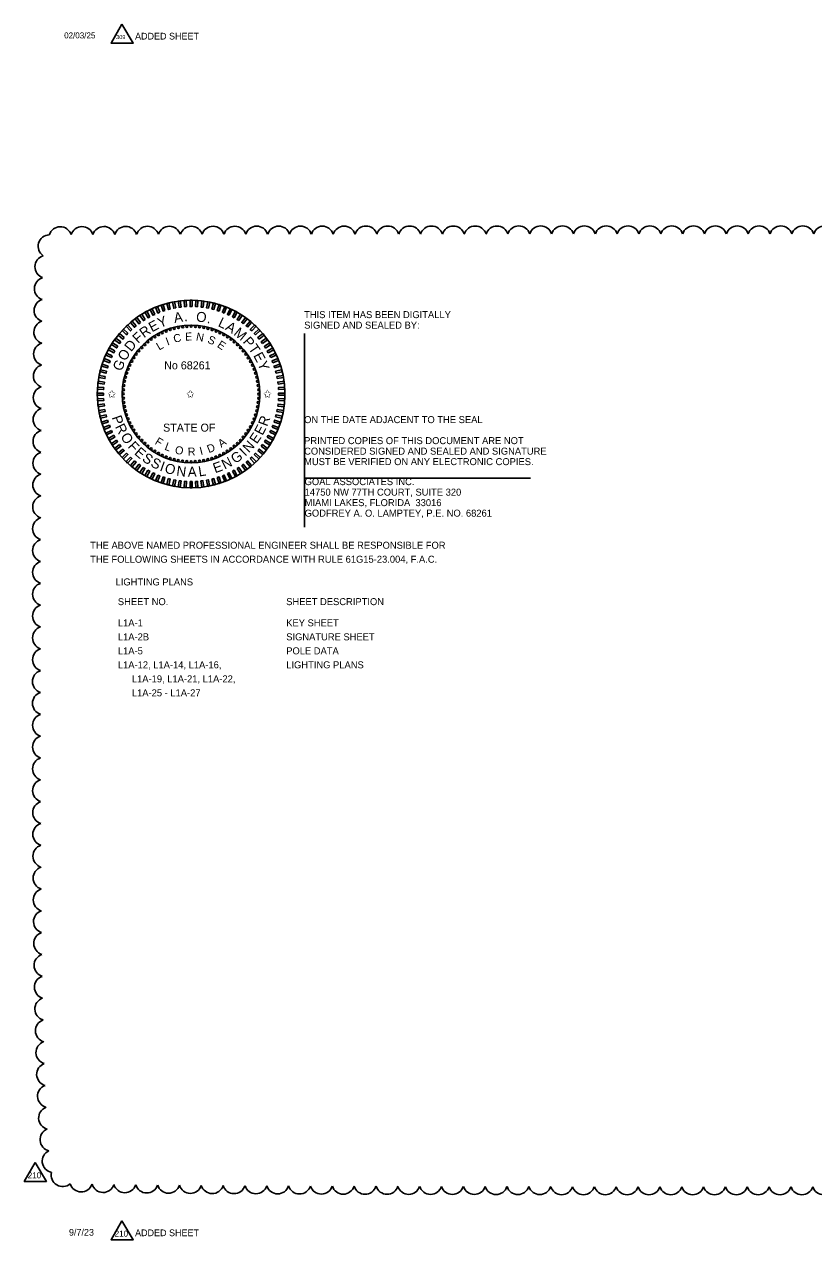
# Model space of a CAD drawing. Extents: x -811.2 to -795.1, y -2238.2 to -2204.
# Drawn here: x -811.16 to -803.27, y -2237.98 to -2225.83 of the extents above; entities that cross this region are included whole.
import ezdxf

# ---------------------------------------------------------------- set-up
doc = ezdxf.new("R2010")
doc.units = 0
for name, color, linetype in [('AdhocPoint_dp', 7, 'Continuous'), ('Cloud_dp', 7, 'Continuous'), ('PlotBorder_dp', 7, 'Continuous'), ('TextMinor', 7, 'Continuous'), ('TextMisc', 7, 'Continuous'), ('TextShtNo', 7, 'Continuous')]:
    doc.layers.add(name, color=color, linetype=linetype)

msp = doc.modelspace()

# ---------------------------------------------------------------- linework, layer by layer
at = {"layer": 'AdhocPoint_dp'}
for p, q in [((-808.355, -2228.92), (-808.355, -2230.855)), ((-808.355, -2230.365), (-806.098, -2230.365))]:
    msp.add_line(p, q, dxfattribs=at)
at = {"layer": 'Cloud_dp'}
for points in [[(-810.181, -2225.827), (-810.289, -2226.015), (-810.068, -2226.015)], [(-811.049, -2237.21), (-811.157, -2237.398), (-810.937, -2237.398)], [(-810.181, -2237.792), (-810.289, -2237.98), (-810.068, -2237.98)]]:
    msp.add_lwpolyline(points, close=True, dxfattribs=at)
for centre, start, end in [((-810.905, -2228.046), 91.4771, 236.4771), ((-810.798, -2227.965), 18.0566, 163.0566), ((-810.58, -2227.964), 17.7998, 162.7998), ((-810.362, -2227.963), 17.7187, 162.7187), ((-810.143, -2227.962), 17.6743, 162.6743), ((-809.925, -2227.961), 17.6451, 162.6451), ((-809.707, -2227.961), 17.624, 162.624), ((-809.488, -2227.961), 17.6079, 162.6079), ((-809.27, -2227.96), 17.5951, 162.5951), ((-809.052, -2227.96), 17.5845, 162.5845), ((-808.834, -2227.959), 17.5756, 162.5756), ((-808.615, -2227.959), 17.568, 162.568), ((-808.397, -2227.959), 17.5614, 162.5614), ((-808.179, -2227.959), 17.5556, 162.5556), ((-807.96, -2227.959), 17.5505, 162.5505), ((-807.742, -2227.958), 17.5459, 162.5459), ((-807.524, -2227.958), 17.5417, 162.5417), ((-807.305, -2227.958), 17.5379, 162.5379), ((-807.087, -2227.958), 17.5344, 162.5344), ((-806.869, -2227.958), 17.5313, 162.5313), ((-806.65, -2227.958), 17.5283, 162.5283), ((-806.432, -2227.958), 17.5256, 162.5256), ((-806.214, -2227.957), 17.5231, 162.5231), ((-805.995, -2227.957), 17.5207, 162.5207), ((-805.777, -2227.957), 17.5185, 162.5185), ((-805.559, -2227.957), 17.5164, 162.5164), ((-805.34, -2227.957), 17.5145, 162.5145), ((-805.122, -2227.957), 17.5126, 162.5126), ((-804.904, -2227.957), 17.5109, 162.5109), ((-804.685, -2227.957), 17.5092, 162.5092), ((-804.467, -2227.957), 17.5077, 162.5077), ((-804.249, -2227.957), 17.5062, 162.5062), ((-804.03, -2227.957), 17.5048, 162.5048), ((-803.812, -2227.957), 17.5034, 162.5034), ((-803.594, -2227.957), 17.5021, 162.5021), ((-803.375, -2227.957), 17.5009, 162.5009), ((-803.157, -2227.957), 17.5, 162.5), ((-810.937, -2228.252), 105.908, 250.908), ((-810.942, -2228.47), 106.4168, 251.4168), ((-810.945, -2228.688), 106.6762, 251.6762), ((-810.948, -2228.906), 106.841, 251.841), ((-810.95, -2229.124), 106.9576, 251.9576), ((-810.952, -2229.343), 107.0457, 252.0457), ((-810.954, -2229.561), 107.1154, 252.1154), ((-810.955, -2229.779), 107.1722, 252.1722), ((-810.956, -2229.998), 107.2198, 252.2198), ((-810.957, -2230.216), 107.2603, 252.2603), ((-810.958, -2230.434), 107.2954, 252.2954), ((-810.959, -2230.652), 107.3262, 252.3262), ((-810.96, -2230.871), 107.3535, 252.3535), ((-810.96, -2231.089), 107.3779, 252.3779), ((-810.96, -2231.307), 107.3998, 252.3998), ((-810.961, -2231.526), 107.4198, 252.4198), ((-810.961, -2231.744), 107.438, 252.438), ((-810.961, -2231.962), 107.4547, 252.4547), ((-810.961, -2232.181), 107.4701, 252.4701), ((-810.962, -2232.399), 107.4843, 252.4843), ((-810.962, -2232.617), 107.499, 252.499), ((-810.961, -2232.836), 107.5356, 252.5356), ((-810.961, -2233.054), 107.5822, 252.5822), ((-810.961, -2233.272), 107.6325, 252.6325), ((-810.96, -2233.49), 107.6869, 252.6869), ((-810.959, -2233.709), 107.7461, 252.7461), ((-810.958, -2233.927), 107.8108, 252.8108), ((-810.957, -2234.145), 107.8818, 252.8818), ((-810.955, -2234.364), 107.9604, 252.9604), ((-810.954, -2234.582), 108.0479, 253.0479), ((-810.951, -2234.8), 108.1461, 253.1461), ((-810.949, -2235.018), 108.2576, 253.2576), ((-810.945, -2235.237), 108.3854, 253.3854), ((-810.942, -2235.455), 108.534, 253.534), ((-810.938, -2235.673), 108.7099, 253.7099), ((-810.932, -2235.891), 108.9225, 253.9225), ((-810.927, -2236.109), 109.1867, 254.1867), ((-810.92, -2236.327), 109.5275, 254.5275), ((-810.911, -2236.545), 109.9909, 254.9909), ((-810.9, -2236.763), 110.6749, 255.6749), ((-810.886, -2236.98), 111.8417, 256.8417), ((-810.864, -2237.195), 114.6718, 259.6718), ((-810.774, -2237.335), 166.2299, 311.2299), ((-810.588, -2237.389), 196.1072, 341.1072), ((-810.37, -2237.394), 196.5738, 341.5738), ((-810.152, -2237.397), 196.7877, 341.7877), ((-809.934, -2237.399), 196.9179, 341.9179), ((-809.715, -2237.401), 197.008, 342.008), ((-809.497, -2237.403), 197.075, 342.075), ((-809.279, -2237.405), 197.1274, 342.1274), ((-809.061, -2237.406), 197.1699, 342.1699), ((-808.842, -2237.407), 197.2052, 342.2052), ((-808.624, -2237.408), 197.2352, 342.2352), ((-808.406, -2237.409), 197.261, 342.261), ((-808.187, -2237.41), 197.2836, 342.2836), ((-807.969, -2237.411), 197.3036, 342.3036), ((-807.751, -2237.412), 197.3214, 342.3214), ((-807.532, -2237.412), 197.3374, 342.3374), ((-807.314, -2237.413), 197.3519, 342.3519), ((-807.096, -2237.413), 197.3651, 342.3651), ((-806.878, -2237.414), 197.3773, 342.3773), ((-806.659, -2237.414), 197.3884, 342.3884), ((-806.441, -2237.415), 197.3987, 342.3987), ((-806.223, -2237.415), 197.4083, 342.4083), ((-806.004, -2237.415), 197.4172, 342.4172), ((-805.786, -2237.416), 197.4256, 342.4256), ((-805.568, -2237.416), 197.4334, 342.4334), ((-805.349, -2237.416), 197.4407, 342.4407), ((-805.131, -2237.417), 197.4476, 342.4476), ((-804.913, -2237.417), 197.4542, 342.4542), ((-804.694, -2237.417), 197.4604, 342.4604), ((-804.476, -2237.417), 197.4662, 342.4662), ((-804.258, -2237.417), 197.4718, 342.4718), ((-804.039, -2237.417), 197.4771, 342.4771), ((-803.821, -2237.417), 197.4821, 342.4821), ((-803.603, -2237.417), 197.487, 342.487), ((-803.384, -2237.417), 197.4916, 342.4916), ((-803.166, -2237.417), 197.496, 342.496)]:
    msp.add_arc(centre, 0.114, start, end, dxfattribs=at)
at = {"layer": 'TextMinor'}
for radius in [0.938, 0.688]:
    msp.add_circle((-809.49, -2229.524), radius, dxfattribs=at)
at = {"layer": 'TextShtNo'}
for p, q in [((-809.5, -2230.461), (-809.5, -2230.399)), ((-809.49, -2230.461), (-809.49, -2230.399)), ((-809.48, -2230.461), (-809.48, -2230.399))]:
    msp.add_line(p, q, dxfattribs=at)
for points in [[(-809.853, -2228.728), (-809.872, -2228.736), (-809.898, -2228.68), (-809.88, -2228.671)], [(-809.803, -2228.706), (-809.822, -2228.714), (-809.845, -2228.656), (-809.826, -2228.648)], [(-809.751, -2228.688), (-809.77, -2228.695), (-809.789, -2228.635), (-809.77, -2228.629)], [(-809.698, -2228.674), (-809.717, -2228.679), (-809.733, -2228.618), (-809.713, -2228.613)], [(-809.644, -2228.662), (-809.664, -2228.666), (-809.676, -2228.605), (-809.656, -2228.601)], [(-809.59, -2228.654), (-809.61, -2228.657), (-809.618, -2228.595), (-809.598, -2228.592)], [(-809.535, -2228.65), (-809.555, -2228.651), (-809.559, -2228.589), (-809.539, -2228.588)], [(-809.48, -2228.649), (-809.5, -2228.649), (-809.5, -2228.586), (-809.48, -2228.586)], [(-809.425, -2228.651), (-809.445, -2228.65), (-809.441, -2228.588), (-809.421, -2228.589)], [(-809.37, -2228.657), (-809.39, -2228.654), (-809.383, -2228.592), (-809.363, -2228.595)], [(-809.316, -2228.666), (-809.336, -2228.662), (-809.324, -2228.601), (-809.304, -2228.605)], [(-809.263, -2228.679), (-809.282, -2228.674), (-809.267, -2228.613), (-809.247, -2228.618)], [(-809.21, -2228.695), (-809.229, -2228.689), (-809.21, -2228.629), (-809.191, -2228.635)], [(-809.159, -2228.714), (-809.177, -2228.707), (-809.154, -2228.649), (-809.136, -2228.656)], [(-809.108, -2228.736), (-809.127, -2228.728), (-809.1, -2228.671), (-809.082, -2228.68)], [(-810.04, -2228.843), (-810.056, -2228.856), (-810.095, -2228.808), (-810.08, -2228.795)], [(-809.996, -2228.81), (-810.013, -2228.822), (-810.049, -2228.771), (-810.033, -2228.759)], [(-809.95, -2228.78), (-809.967, -2228.79), (-810.001, -2228.738), (-809.984, -2228.727)], [(-809.903, -2228.752), (-809.92, -2228.762), (-809.951, -2228.707), (-809.933, -2228.697)], [(-809.06, -2228.762), (-809.077, -2228.752), (-809.047, -2228.697), (-809.03, -2228.707)], [(-809.013, -2228.79), (-809.03, -2228.78), (-808.996, -2228.727), (-808.979, -2228.738)], [(-808.968, -2228.822), (-808.984, -2228.81), (-808.947, -2228.76), (-808.931, -2228.771)], [(-808.925, -2228.856), (-808.94, -2228.843), (-808.9, -2228.795), (-808.885, -2228.808)], [(-810.158, -2228.958), (-810.171, -2228.974), (-810.219, -2228.934), (-810.206, -2228.918)], [(-810.121, -2228.917), (-810.135, -2228.932), (-810.18, -2228.889), (-810.167, -2228.875)], [(-810.082, -2228.879), (-810.096, -2228.893), (-810.139, -2228.847), (-810.124, -2228.833)], [(-808.884, -2228.893), (-808.898, -2228.879), (-808.856, -2228.834), (-808.841, -2228.847)], [(-808.845, -2228.932), (-808.859, -2228.918), (-808.814, -2228.875), (-808.8, -2228.89)], [(-808.809, -2228.974), (-808.822, -2228.958), (-808.774, -2228.919), (-808.761, -2228.934)], [(-810.223, -2229.046), (-810.234, -2229.063), (-810.287, -2229.03), (-810.276, -2229.013)], [(-810.192, -2229.001), (-810.204, -2229.018), (-810.254, -2228.981), (-810.243, -2228.965)], [(-808.776, -2229.018), (-808.788, -2229.001), (-808.738, -2228.965), (-808.726, -2228.981)], [(-808.746, -2229.064), (-808.757, -2229.047), (-808.704, -2229.013), (-808.693, -2229.03)], [(-810.278, -2229.142), (-810.286, -2229.16), (-810.343, -2229.134), (-810.334, -2229.115)], [(-810.252, -2229.093), (-810.262, -2229.111), (-810.316, -2229.081), (-810.307, -2229.063)], [(-808.718, -2229.111), (-808.728, -2229.094), (-808.673, -2229.063), (-808.664, -2229.081)], [(-808.694, -2229.16), (-808.703, -2229.142), (-808.646, -2229.116), (-808.638, -2229.134)], [(-810.335, -2229.296), (-810.34, -2229.316), (-810.401, -2229.3), (-810.396, -2229.281)], [(-810.319, -2229.244), (-810.325, -2229.263), (-810.385, -2229.244), (-810.379, -2229.224)], [(-810.3, -2229.192), (-810.307, -2229.211), (-810.365, -2229.188), (-810.358, -2229.169)], [(-808.673, -2229.211), (-808.68, -2229.192), (-808.622, -2229.169), (-808.615, -2229.188)], [(-808.655, -2229.263), (-808.661, -2229.244), (-808.602, -2229.225), (-808.595, -2229.244)], [(-808.64, -2229.316), (-808.645, -2229.297), (-808.585, -2229.281), (-808.58, -2229.301)], [(-810.357, -2229.404), (-810.36, -2229.424), (-810.421, -2229.416), (-810.419, -2229.396)], [(-810.348, -2229.35), (-810.352, -2229.37), (-810.413, -2229.358), (-810.409, -2229.338)], [(-808.629, -2229.37), (-808.632, -2229.35), (-808.571, -2229.338), (-808.567, -2229.358)], [(-808.621, -2229.424), (-808.623, -2229.404), (-808.561, -2229.396), (-808.559, -2229.416)], [(-810.365, -2229.514), (-810.365, -2229.534), (-810.428, -2229.534), (-810.428, -2229.514)], [(-810.363, -2229.459), (-810.364, -2229.479), (-810.426, -2229.475), (-810.425, -2229.455)], [(-808.616, -2229.479), (-808.617, -2229.459), (-808.555, -2229.455), (-808.554, -2229.475)], [(-808.615, -2229.534), (-808.615, -2229.514), (-808.553, -2229.514), (-808.553, -2229.534)], [(-810.364, -2229.569), (-810.363, -2229.589), (-810.425, -2229.593), (-810.426, -2229.573)], [(-810.36, -2229.623), (-810.357, -2229.643), (-810.419, -2229.651), (-810.421, -2229.631)], [(-808.623, -2229.644), (-808.621, -2229.624), (-808.559, -2229.631), (-808.561, -2229.651)], [(-808.617, -2229.589), (-808.616, -2229.569), (-808.554, -2229.573), (-808.555, -2229.593)], [(-810.352, -2229.678), (-810.348, -2229.698), (-810.409, -2229.709), (-810.413, -2229.689)], [(-810.34, -2229.732), (-810.335, -2229.751), (-810.396, -2229.767), (-810.401, -2229.747)], [(-808.645, -2229.751), (-808.64, -2229.732), (-808.58, -2229.747), (-808.585, -2229.767)], [(-808.632, -2229.698), (-808.629, -2229.678), (-808.567, -2229.69), (-808.571, -2229.709)], [(-810.325, -2229.785), (-810.319, -2229.804), (-810.379, -2229.823), (-810.385, -2229.804)], [(-810.307, -2229.836), (-810.3, -2229.855), (-810.358, -2229.878), (-810.366, -2229.859)], [(-810.286, -2229.887), (-810.278, -2229.905), (-810.334, -2229.932), (-810.343, -2229.914)], [(-808.703, -2229.906), (-808.694, -2229.887), (-808.638, -2229.914), (-808.646, -2229.932)], [(-808.68, -2229.855), (-808.673, -2229.837), (-808.615, -2229.86), (-808.622, -2229.878)], [(-808.661, -2229.804), (-808.655, -2229.785), (-808.595, -2229.804), (-808.602, -2229.823)], [(-810.262, -2229.936), (-810.252, -2229.954), (-810.307, -2229.984), (-810.317, -2229.967)], [(-810.234, -2229.984), (-810.224, -2230.001), (-810.276, -2230.035), (-810.287, -2230.018)], [(-808.757, -2230.001), (-808.746, -2229.984), (-808.693, -2230.018), (-808.704, -2230.035)], [(-808.728, -2229.954), (-808.719, -2229.937), (-808.664, -2229.967), (-808.674, -2229.984)], [(-810.204, -2230.03), (-810.192, -2230.046), (-810.243, -2230.083), (-810.255, -2230.067)], [(-810.171, -2230.074), (-810.158, -2230.089), (-810.206, -2230.129), (-810.219, -2230.114)], [(-810.135, -2230.115), (-810.121, -2230.13), (-810.167, -2230.173), (-810.18, -2230.158)], [(-808.859, -2230.13), (-808.845, -2230.116), (-808.8, -2230.158), (-808.814, -2230.173)], [(-808.822, -2230.089), (-808.81, -2230.074), (-808.761, -2230.114), (-808.774, -2230.129)], [(-808.788, -2230.046), (-808.776, -2230.03), (-808.726, -2230.067), (-808.738, -2230.083)], [(-810.097, -2230.155), (-810.082, -2230.169), (-810.125, -2230.214), (-810.139, -2230.2)], [(-810.056, -2230.192), (-810.04, -2230.204), (-810.08, -2230.253), (-810.096, -2230.24)], [(-810.013, -2230.226), (-809.996, -2230.238), (-810.033, -2230.288), (-810.049, -2230.276)], [(-808.984, -2230.238), (-808.968, -2230.226), (-808.931, -2230.276), (-808.947, -2230.288)], [(-808.94, -2230.205), (-808.925, -2230.192), (-808.885, -2230.24), (-808.9, -2230.253)], [(-808.899, -2230.169), (-808.884, -2230.155), (-808.841, -2230.2), (-808.856, -2230.214)], [(-809.968, -2230.257), (-809.951, -2230.268), (-809.984, -2230.321), (-810.001, -2230.31)], [(-809.921, -2230.286), (-809.903, -2230.295), (-809.933, -2230.35), (-809.951, -2230.34)], [(-809.872, -2230.311), (-809.854, -2230.32), (-809.88, -2230.376), (-809.898, -2230.368)], [(-809.822, -2230.334), (-809.803, -2230.341), (-809.826, -2230.399), (-809.845, -2230.392)], [(-809.77, -2230.353), (-809.751, -2230.359), (-809.77, -2230.419), (-809.789, -2230.412)], [(-809.718, -2230.369), (-809.698, -2230.374), (-809.714, -2230.434), (-809.733, -2230.429)], [(-809.282, -2230.374), (-809.263, -2230.369), (-809.247, -2230.429), (-809.267, -2230.434)], [(-809.229, -2230.359), (-809.21, -2230.353), (-809.191, -2230.412), (-809.21, -2230.419)], [(-809.177, -2230.341), (-809.159, -2230.334), (-809.136, -2230.392), (-809.154, -2230.399)], [(-809.127, -2230.32), (-809.108, -2230.311), (-809.082, -2230.368), (-809.1, -2230.376)], [(-809.077, -2230.296), (-809.06, -2230.286), (-809.03, -2230.341), (-809.047, -2230.35)], [(-809.03, -2230.268), (-809.013, -2230.257), (-808.979, -2230.31), (-808.996, -2230.321)], [(-809.664, -2230.381), (-809.644, -2230.385), (-809.656, -2230.447), (-809.676, -2230.443)], [(-809.61, -2230.391), (-809.59, -2230.393), (-809.598, -2230.455), (-809.618, -2230.453)], [(-809.555, -2230.396), (-809.535, -2230.398), (-809.539, -2230.46), (-809.559, -2230.459)], [(-809.5, -2230.399), (-809.48, -2230.399), (-809.48, -2230.461), (-809.5, -2230.461)], [(-809.445, -2230.398), (-809.425, -2230.397), (-809.421, -2230.459), (-809.441, -2230.46)], [(-809.391, -2230.393), (-809.371, -2230.391), (-809.363, -2230.453), (-809.383, -2230.455)], [(-809.336, -2230.385), (-809.316, -2230.381), (-809.305, -2230.443), (-809.324, -2230.447)]]:
    msp.add_lwpolyline(points, close=True, dxfattribs=at)
for centre in [(-809.778, -2228.911), (-809.739, -2228.894), (-809.699, -2228.879), (-809.658, -2228.868), (-809.617, -2228.858), (-809.574, -2228.852), (-809.532, -2228.848), (-809.49, -2228.846), (-809.447, -2228.848), (-809.405, -2228.852), (-809.363, -2228.858), (-809.321, -2228.868), (-809.28, -2228.88), (-809.24, -2228.894), (-809.201, -2228.911), (-809.953, -2229.03), (-809.922, -2229.001), (-809.888, -2228.975), (-809.853, -2228.952), (-809.816, -2228.93), (-809.163, -2228.93), (-809.127, -2228.952), (-809.091, -2228.976), (-809.058, -2229.002), (-809.026, -2229.03), (-810.062, -2229.16), (-810.038, -2229.125), (-810.012, -2229.092), (-809.984, -2229.06), (-808.996, -2229.06), (-808.968, -2229.092), (-808.942, -2229.126), (-808.918, -2229.161), (-810.12, -2229.274), (-810.103, -2229.235), (-810.084, -2229.197), (-808.896, -2229.198), (-808.877, -2229.236), (-808.86, -2229.275), (-810.155, -2229.396), (-810.146, -2229.355), (-810.134, -2229.314), (-808.846, -2229.315), (-808.834, -2229.356), (-808.825, -2229.397), (-810.168, -2229.523), (-810.166, -2229.481), (-810.162, -2229.438), (-808.818, -2229.439), (-808.814, -2229.482), (-808.813, -2229.524), (-810.166, -2229.566), (-810.162, -2229.608), (-810.156, -2229.65), (-808.825, -2229.651), (-808.818, -2229.609), (-808.814, -2229.567), (-810.146, -2229.692), (-810.135, -2229.733), (-810.12, -2229.773), (-808.86, -2229.774), (-808.846, -2229.734), (-808.834, -2229.693), (-810.103, -2229.812), (-810.084, -2229.85), (-810.062, -2229.886), (-808.918, -2229.887), (-808.897, -2229.851), (-808.877, -2229.813), (-810.039, -2229.922), (-810.012, -2229.955), (-809.984, -2229.987), (-809.954, -2230.017), (-809.027, -2230.018), (-808.997, -2229.988), (-808.968, -2229.956), (-808.942, -2229.922), (-809.922, -2230.045), (-809.889, -2230.072), (-809.854, -2230.096), (-809.817, -2230.117), (-809.779, -2230.137), (-809.202, -2230.137), (-809.164, -2230.118), (-809.128, -2230.096), (-809.092, -2230.072), (-809.059, -2230.046), (-809.74, -2230.154), (-809.7, -2230.168), (-809.659, -2230.18), (-809.618, -2230.189), (-809.576, -2230.196), (-809.533, -2230.2), (-809.49, -2230.201), (-809.448, -2230.2), (-809.406, -2230.196), (-809.364, -2230.189), (-809.322, -2230.18), (-809.281, -2230.168), (-809.241, -2230.154)]:
    msp.add_circle(centre, 0.01, dxfattribs=at)

# ---------------------------------------------------------------- texts
at = {"layer": 'Cloud_dp'}
for s, height, p in [('309', 0.04, (-810.239, -2225.975)), ('210', 0.06, (-811.123, -2237.367)), ('210', 0.06, (-810.254, -2237.95))]:
    msp.add_text(s, height=height, rotation=0, dxfattribs=at).set_placement(p)
at = {"layer": 'PlotBorder_dp'}
for s, p in [('THIS ITEM HAS BEEN DIGITALLY', (-808.36, -2228.765)), ('SIGNED AND SEALED BY:', (-808.36, -2228.87)), ('ON THE DATE ADJACENT TO THE SEAL', (-808.36, -2229.815)), ('PRINTED COPIES OF THIS DOCUMENT ARE NOT ', (-808.36, -2230.025)), ('CONSIDERED SIGNED AND SEALED AND SIGNATURE ', (-808.36, -2230.13)), ('MUST BE VERIFIED ON ANY ELECTRONIC COPIES.', (-808.36, -2230.235)), ('GOAL ASSOCIATES INC.', (-808.355, -2230.435)), ('14750 NW 77TH COURT, SUITE 320', (-808.355, -2230.54)), ('MIAMI LAKES, FLORIDA  33016', (-808.355, -2230.645)), ('GODFREY A. O. LAMPTEY, P.E. NO. 68261', (-808.355, -2230.75)), ('THE ABOVE NAMED PROFESSIONAL ENGINEER SHALL BE RESPONSIBLE FOR ', (-810.499, -2231.071)), ('THE FOLLOWING SHEETS IN ACCORDANCE WITH RULE 61G15-23.004, F.A.C.', (-810.499, -2231.211)), ('LIGHTING PLANS', (-810.245, -2231.438))]:
    msp.add_text(s, height=0.07, dxfattribs=at).set_placement(p)
at = {"layer": 'TextMinor'}
for s, height, p in [('02/03/25', 0.06, (-810.759, -2225.968)), ('ADDED SHEET', 0.0672, (-810.05, -2225.979))]:
    msp.add_text(s, height=height, dxfattribs=at).set_placement(p)
for s, p in [('9/7/23', (-810.711, -2237.94)), ('ADDED SHEET', (-810.05, -2237.945))]:
    msp.add_text(s, height=0.0672, rotation=360, dxfattribs=at).set_placement(p)
at = {"layer": 'TextMisc'}
for s, p in [('SHEET NO.', (-810.222, -2231.635)), ('SHEET DESCRIPTION', (-808.539, -2231.635)), ('L1A-1', (-810.222, -2231.847)), ('KEY SHEET', (-808.539, -2231.847)), ('L1A-2B', (-810.222, -2231.987)), ('SIGNATURE SHEET', (-808.539, -2231.987)), ('L1A-5', (-810.222, -2232.127)), ('POLE DATA', (-808.539, -2232.127)), ('L1A-12, L1A-14, L1A-16,', (-810.222, -2232.267)), ('LIGHTING PLANS', (-808.539, -2232.267)), ('L1A-19, L1A-21, L1A-22,', (-810.082, -2232.407)), ('L1A-25 - L1A-27', (-810.082, -2232.547))]:
    msp.add_text(s, height=0.07, dxfattribs=at).set_placement(p)
at = {"layer": 'TextShtNo'}
for s, height, rotation, p in [('E', 0.1, 28.1055, (-809.881, -2228.908)), ('Y', 0.1, 21.0633, (-809.802, -2228.864)), ('A', 0.1, 8.8088, (-809.655, -2228.813)), ('.', 0.1, 1.0418, (-809.558, -2228.797)), ('O', 0.1, 352.1877, (-809.445, -2228.796)), ('L', 0.1, 334.6727, (-809.228, -2228.843)), ('F', 0.1, 42.3772, (-810.02, -2229.023)), ('R', 0.1, 35.9269, (-809.961, -2228.967)), ('E', 0.08, 0.4186, (-809.55, -2228.989)), ('N', 0.08, 349.2914, (-809.445, -2228.987)), ('.', 0.1, 343.5268, (-809.336, -2228.811)), ('A', 0.1, 328.4096, (-809.155, -2228.876)), ('M', 0.1, 320.6426, (-809.071, -2228.927)), ('D', 0.1, 50.8569, (-810.089, -2229.107)), ('L', 0.08, 30.4021, (-809.809, -2229.09)), ('I', 0.08, 20.0117, (-809.726, -2229.04)), ('C', 0.08, 12.2025, (-809.658, -2229.012)), ('S', 0.08, 337.0221, (-809.332, -2229.009)), ('E', 0.08, 325.8663, (-809.236, -2229.049)), ('P', 0.1, 311.1966, (-808.978, -2229.004)), ('T', 0.1, 304.4563, (-808.921, -2229.068)), ('O', 0.1, 59.5178, (-810.145, -2229.201)), ('E', 0.1, 297.6315, (-808.871, -2229.138)), ('G', 0.1, 68.0518, (-810.185, -2229.302)), ('Y', 0.1, 290.5893, (-808.828, -2229.217)), ('P', 0.1, 289.4055, (-810.285, -2229.758)), ('R', 0.1, 69.5134, (-808.73, -2229.854)), ('R', 0.1, 296.1458, (-810.252, -2229.85)), ('E', 0.1, 62.4712, (-808.776, -2229.944)), ('O', 0.1, 303.9671, (-810.2, -2229.951)), ('F', 0.1, 312.628, (-810.128, -2230.053)), ('F', 0.08, 328.7241, (-809.858, -2230.02)), ('L', 0.08, 339.2916, (-809.761, -2230.079)), ('A', 0.08, 34.4992, (-809.188, -2230.063)), ('N', 0.1, 47.1788, (-808.912, -2230.118)), ('E', 0.1, 55.4289, (-808.833, -2230.029)), ('E', 0.1, 319.0783, (-810.064, -2230.121)), ('S', 0.1, 326.1206, (-809.987, -2230.187)), ('O', 0.08, 349.6821, (-809.656, -2230.119)), ('R', 0.08, 2.3398, (-809.522, -2230.141)), ('I', 0.08, 14.2037, (-809.394, -2230.134)), ('D', 0.08, 22.0128, (-809.312, -2230.116)), ('G', 0.1, 35.1115, (-809.049, -2230.225)), ('I', 0.1, 43.6456, (-808.95, -2230.152)), ('S', 0.1, 333.193, (-809.902, -2230.243)), ('I', 0.1, 340.2654, (-809.81, -2230.288)), ('O', 0.1, 343.7986, (-809.762, -2230.307)), ('N', 0.1, 352.4595, (-809.641, -2230.339)), ('A', 0.1, 0.7097, (-809.523, -2230.352)), ('L', 0.1, 8.4767, (-809.41, -2230.349)), ('E', 0.1, 19.8191, (-809.25, -2230.317)), ('N', 0.1, 26.8614, (-809.154, -2230.281))]:
    msp.add_text(s, height=height, rotation=rotation, dxfattribs=at).set_placement(p)
for s, p in [('No 68261', (-809.759, -2229.277)), ('✩', (-810.325, -2229.562)), ('✩', (-809.54, -2229.562)), ('✩', (-808.769, -2229.562)), ('STATE OF', (-809.77, -2229.9))]:
    msp.add_text(s, height=0.08, dxfattribs=at).set_placement(p)

doc.saveas('drawing.dxf')
